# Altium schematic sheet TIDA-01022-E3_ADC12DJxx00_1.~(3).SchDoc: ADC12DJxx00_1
size 431 x 279 mm; Date: Not shown in title block; ApprovedBy: Not shown in title block; CheckedBy: Not shown in title block; Author: Not shown in title block; CompanyName: Not shown in title block; DrawnBy: Avinash N; Engineer: Not shown in title block; Organization: Not shown in title block; Address1: Not shown in title block; Address2: Not shown in title block; Address3: Not shown in title block; Address4: Not shown in title block; DocumentNumber: 1; Revision: Use project parameter SCH_Rev; SheetNumber: 6; SheetTotal: 26; PageSetup: Record=PageOptions¦CenterHorizontal=True¦CenterVertical=True¦PrintScale=1.00¦XCorrection=1.00¦YCorrection=1.00¦PrintKind=0¦BorderSize=5000000¦LeftOffset=0¦BottomOffset=0¦Orientation=2¦PaperLength=1000¦PaperWidth=1000¦Scale=100¦PaperSource=15¦PrintQuality=600¦MediaType=1¦DitherType=10¦PaperKind=Letter¦PrintScaleMode=1
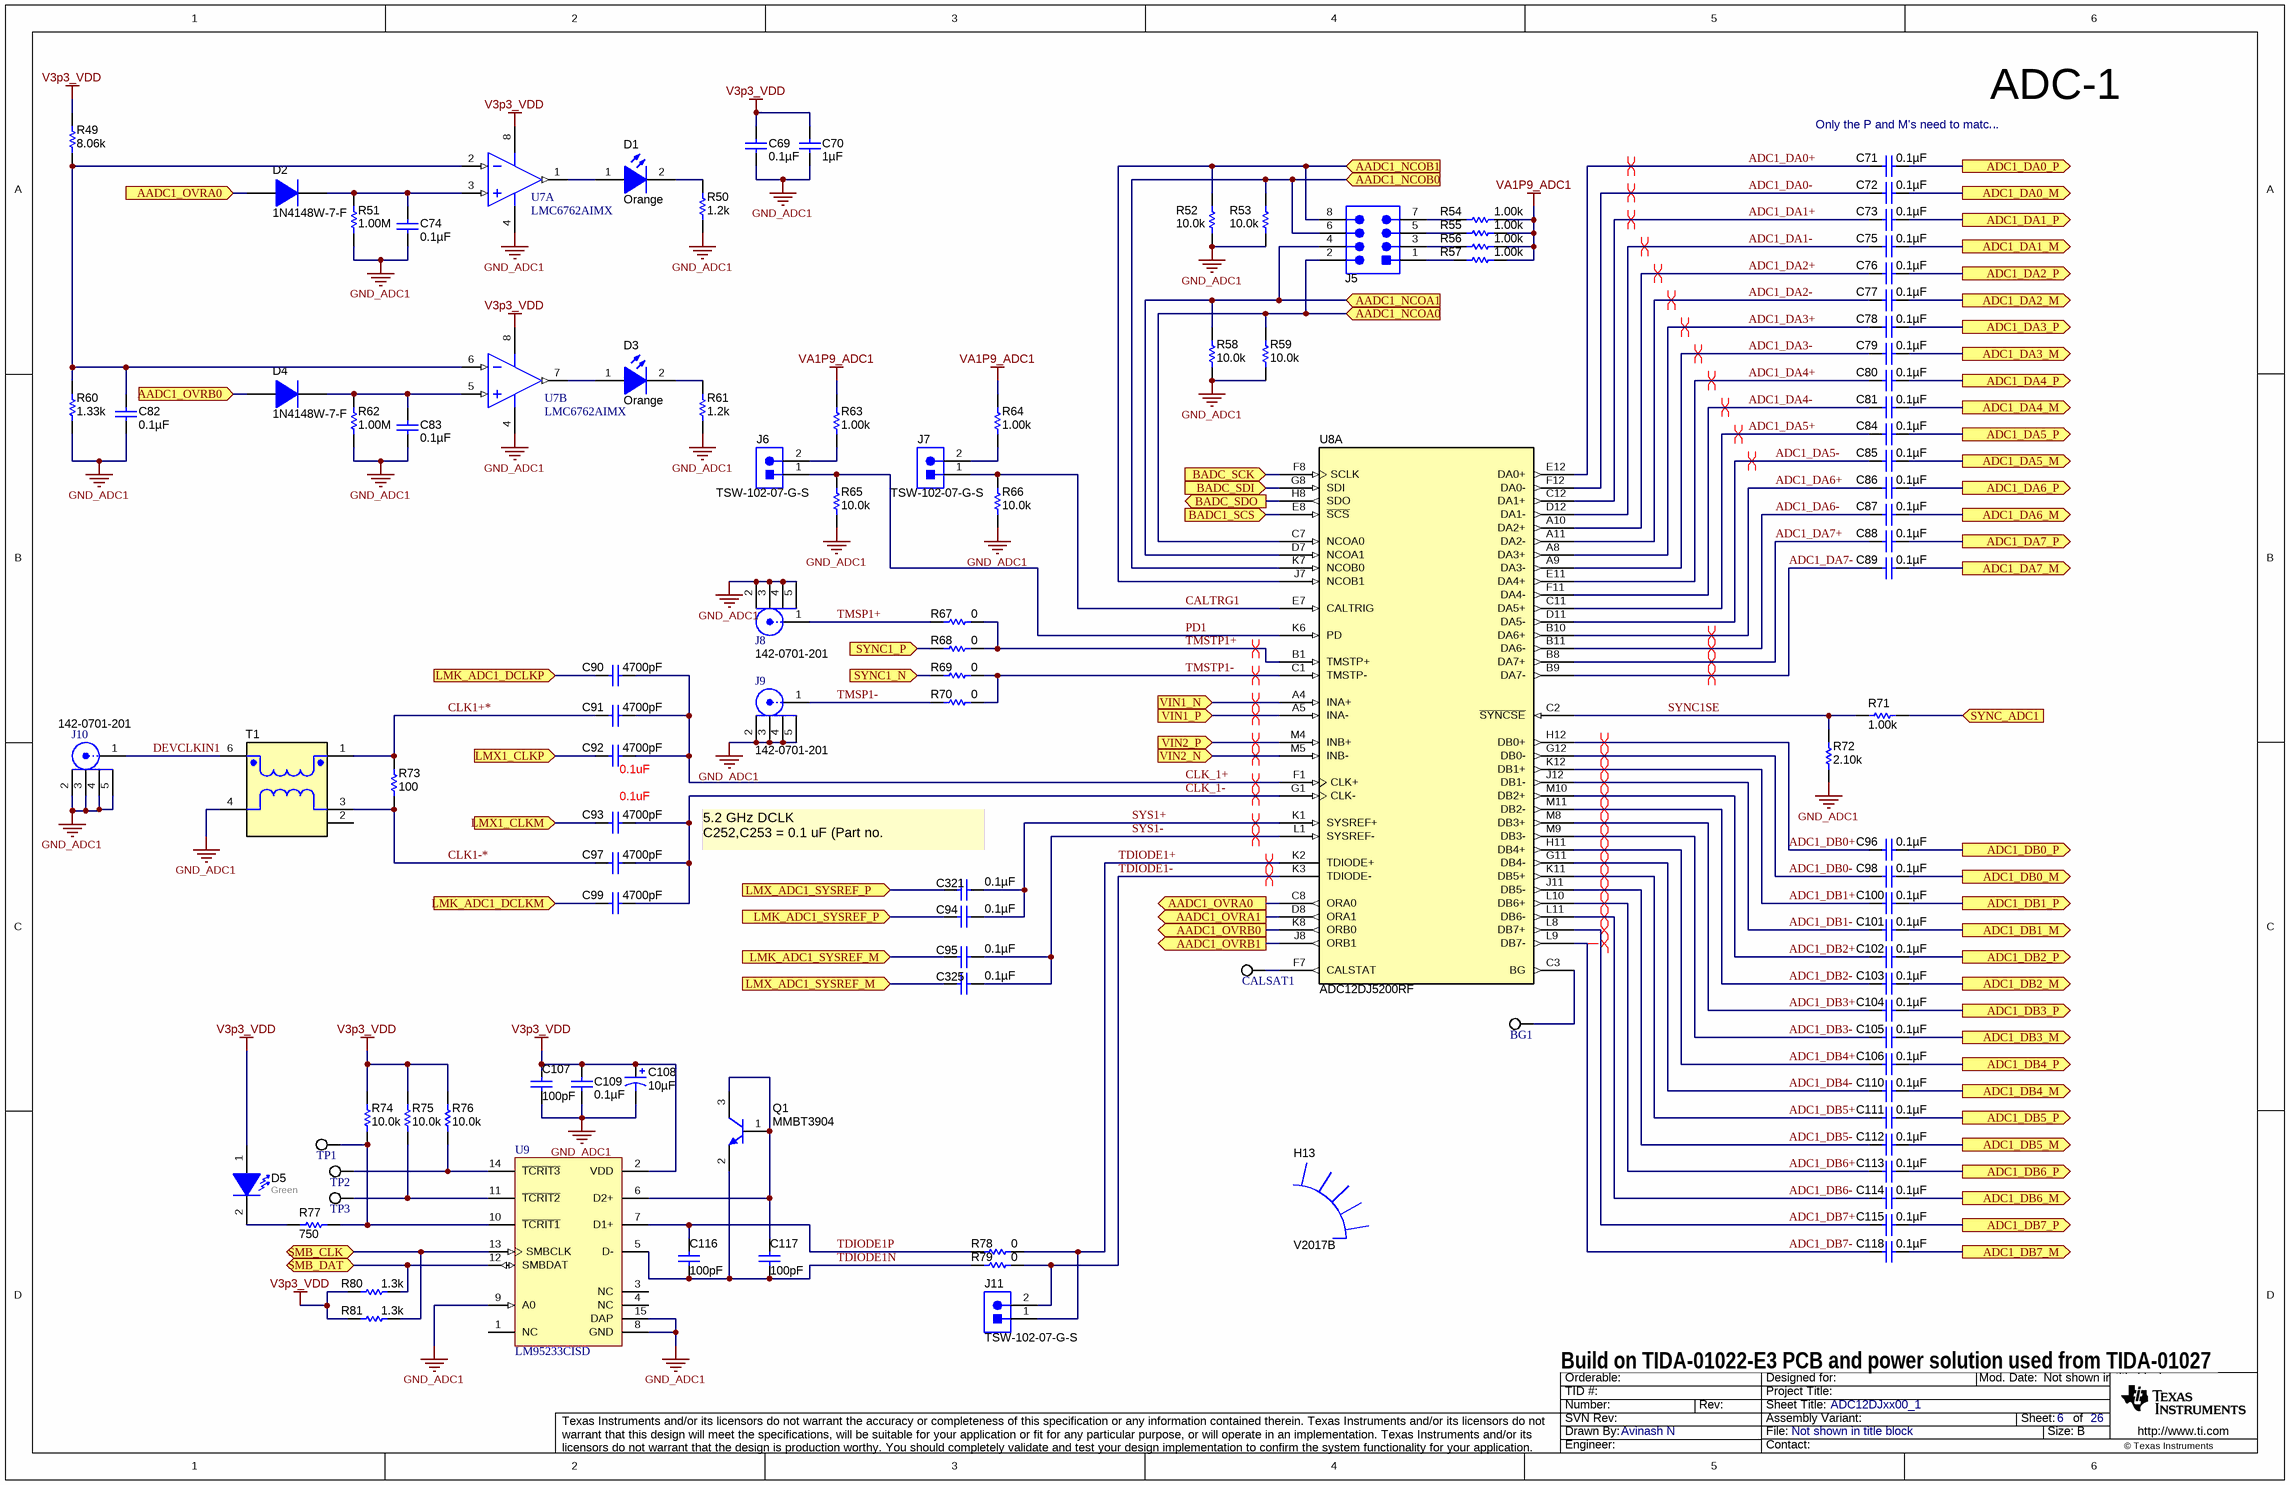
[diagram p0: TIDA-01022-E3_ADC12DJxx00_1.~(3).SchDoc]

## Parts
BG1  5002  [Keystone5002]  (value not drawn)
C69  ValueDisplayed: 0.1µF  [0402]  (hidden comment: C1005X7R1E104M050BB)
C70  ValueDisplayed: 1µF  [0603]  (hidden comment: C1608X5R1A105K080AC)
C71  ValueDisplayed: 0.1µF  [0201_adc]  (hidden comment: GRM033C71A104KE14D)
C72  ValueDisplayed: 0.1µF  [0201_adc]  (hidden comment: GRM033C71A104KE14D)
C73  ValueDisplayed: 0.1µF  [0201_adc]  (hidden comment: GRM033C71A104KE14D)
C74  ValueDisplayed: 0.1µF  [0402]  (hidden comment: C1005X7R1E104M050BB)
C75  ValueDisplayed: 0.1µF  [0201_adc]  (hidden comment: GRM033C71A104KE14D)
C76  ValueDisplayed: 0.1µF  [0201_adc]  (hidden comment: GRM033C71A104KE14D)
C77  ValueDisplayed: 0.1µF  [0201_adc]  (hidden comment: GRM033C71A104KE14D)
C78  ValueDisplayed: 0.1µF  [0201_adc]  (hidden comment: GRM033C71A104KE14D)
C79  ValueDisplayed: 0.1µF  [0201_adc]  (hidden comment: GRM033C71A104KE14D)
C80  ValueDisplayed: 0.1µF  [0201_adc]  (hidden comment: GRM033C71A104KE14D)
C81  ValueDisplayed: 0.1µF  [0201_adc]  (hidden comment: GRM033C71A104KE14D)
C82  ValueDisplayed: 0.1µF  [0402]  (hidden comment: C1005X7R1E104M050BB)
C83  ValueDisplayed: 0.1µF  [0402]  (hidden comment: C1005X7R1E104M050BB)
C84  ValueDisplayed: 0.1µF  [0201_adc]  (hidden comment: GRM033C71A104KE14D)
C85  ValueDisplayed: 0.1µF  [0201_adc]  (hidden comment: GRM033C71A104KE14D)
C86  ValueDisplayed: 0.1µF  [0201_adc]  (hidden comment: GRM033C71A104KE14D)
C87  ValueDisplayed: 0.1µF  [0201_adc]  (hidden comment: GRM033C71A104KE14D)
C88  ValueDisplayed: 0.1µF  [0201_adc]  (hidden comment: GRM033C71A104KE14D)
C89  ValueDisplayed: 0.1µF  [0201_adc]  (hidden comment: GRM033C71A104KE14D)
C90  ValueDisplayed: 4700pF  [0402]  (hidden comment: GRM155R71H472KA01D)
C91  ValueDisplayed: 4700pF  [0402]  (hidden comment: GRM155R71H472KA01D)
C92  ValueDisplayed: 4700pF  [0402]  (hidden comment: GRM155R71H472KA01D)
C93  ValueDisplayed: 4700pF  [0402]  (hidden comment: GRM155R71H472KA01D)
C94  ValueDisplayed: 0.1µF  [0402]  (hidden comment: C1005X7R1E104M050BB)
C95  ValueDisplayed: 0.1µF  [0402]  (hidden comment: C1005X7R1E104M050BB)
C96  ValueDisplayed: 0.1µF  [0201_adc]  (hidden comment: GRM033C71A104KE14D)
C97  ValueDisplayed: 4700pF  [0402]  (hidden comment: GRM155R71H472KA01D)
C98  ValueDisplayed: 0.1µF  [0201_adc]  (hidden comment: GRM033C71A104KE14D)
C99  ValueDisplayed: 4700pF  [0402]  (hidden comment: GRM155R71H472KA01D)
C100  ValueDisplayed: 0.1µF  [0201_adc]  (hidden comment: GRM033C71A104KE14D)
C101  ValueDisplayed: 0.1µF  [0201_adc]  (hidden comment: GRM033C71A104KE14D)
C102  ValueDisplayed: 0.1µF  [0201_adc]  (hidden comment: GRM033C71A104KE14D)
C103  ValueDisplayed: 0.1µF  [0201_adc]  (hidden comment: GRM033C71A104KE14D)
C104  ValueDisplayed: 0.1µF  [0201_adc]  (hidden comment: GRM033C71A104KE14D)
C105  ValueDisplayed: 0.1µF  [0201_adc]  (hidden comment: GRM033C71A104KE14D)
C106  ValueDisplayed: 0.1µF  [0201_adc]  (hidden comment: GRM033C71A104KE14D)
C107  ValueDisplayed: 100pF  [0402]  (hidden comment: GRM1555C1H101JA01D)
C108  ValueDisplayed: 10µF  [3528-21]  (hidden comment: 293D106X0010B2TE3)
C109  ValueDisplayed: 0.1µF  [0402]  (hidden comment: C1005X7R1E104M050BB)
C110  ValueDisplayed: 0.1µF  [0201_adc]  (hidden comment: GRM033C71A104KE14D)
C111  ValueDisplayed: 0.1µF  [0201_adc]  (hidden comment: GRM033C71A104KE14D)
C112  ValueDisplayed: 0.1µF  [0201_adc]  (hidden comment: GRM033C71A104KE14D)
C113  ValueDisplayed: 0.1µF  [0201_adc]  (hidden comment: GRM033C71A104KE14D)
C114  ValueDisplayed: 0.1µF  [0201_adc]  (hidden comment: GRM033C71A104KE14D)
C115  ValueDisplayed: 0.1µF  [0201_adc]  (hidden comment: GRM033C71A104KE14D)
C116  ValueDisplayed: 100pF  [0402]  (hidden comment: GRM1555C1H101JA01D)
C117  ValueDisplayed: 100pF  [0402]  (hidden comment: GRM1555C1H101JA01D)
C118  ValueDisplayed: 0.1µF  [0201_adc]  (hidden comment: GRM033C71A104KE14D)
C321  ValueDisplayed: 0.1µF  [0402]  (hidden comment: C1005X7R1E104M050BB)
C325  ValueDisplayed: 0.1µF  [0402]  (hidden comment: C1005X7R1E104M050BB)
CALSAT1  5002  [Keystone5002]  (value not drawn)
D1  value Orange  [LED_LTST-C190]  (hidden comment: LTST-C190KFKT)
D2  1N4148W-7-F  [SOD-123]
D3  value Orange  [LED_LTST-C190]  (hidden comment: LTST-C190KFKT)
D4  1N4148W-7-F  [SOD-123]
D5  value Green  [LED_LTST-C190]  (hidden comment: LTST-C190GKT)
H13  V2017B  [ASMN_V2017B]  (mechanical)
J5  TSW-104-07-G-D  [TSW-104-07-G-D]  (value not drawn)
J6  TSW-102-07-G-S  [TSW-102-07-G-S]
J7  TSW-102-07-G-S  [TSW-102-07-G-S]
J8  142-0701-201  [Johnson_142-0701-20x]
J9  142-0701-201  [Johnson_142-0701-20x]
J10  142-0701-201  [Johnson_142-0701-20x]
J11  TSW-102-07-G-S  [TSW-102-07-G-S]
Q1  MMBT3904  [SOT-23]
R49  ValueDisplayed: 8.06k  [0402]  (hidden comment: CRCW04028K06FKED)
R50  ValueDisplayed: 1.2k  [0402]  (hidden comment: CRCW04021K20JNED)
R51  ValueDisplayed: 1.00M  [0402]  (hidden comment: ERJ-2RKF1004X)
R52  ValueDisplayed: 10.0k  [0402]  (hidden comment: ERJ-2RKF1002X)
R53  ValueDisplayed: 10.0k  [0402]  (hidden comment: ERJ-2RKF1002X)
R54  ValueDisplayed: 1.00k  [0402]  (hidden comment: ERJ-2RKF1001X)
R55  ValueDisplayed: 1.00k  [0402]  (hidden comment: ERJ-2RKF1001X)
R56  ValueDisplayed: 1.00k  [0402]  (hidden comment: ERJ-2RKF1001X)
R57  ValueDisplayed: 1.00k  [0402]  (hidden comment: ERJ-2RKF1001X)
R58  ValueDisplayed: 10.0k  [0402]  (hidden comment: ERJ-2RKF1002X)
R59  ValueDisplayed: 10.0k  [0402]  (hidden comment: ERJ-2RKF1002X)
R60  ValueDisplayed: 1.33k  [0402]  (hidden comment: CRCW04021K33FKED)
R61  ValueDisplayed: 1.2k  [0402]  (hidden comment: CRCW04021K20JNED)
R62  ValueDisplayed: 1.00M  [0402]  (hidden comment: ERJ-2RKF1004X)
R63  ValueDisplayed: 1.00k  [0402]  (hidden comment: ERJ-2RKF1001X)
R64  ValueDisplayed: 1.00k  [0402]  (hidden comment: ERJ-2RKF1001X)
R65  ValueDisplayed: 10.0k  [0402]  (hidden comment: ERJ-2RKF1002X)
R66  ValueDisplayed: 10.0k  [0402]  (hidden comment: ERJ-2RKF1002X)
R67  ValueDisplayed: 0  [0402]  (hidden comment: CRCW04020000Z0ED)
R68  ValueDisplayed: 0  [0402]  (hidden comment: CRCW04020000Z0ED)
R69  ValueDisplayed: 0  [0402]  (hidden comment: CRCW04020000Z0ED)
R70  ValueDisplayed: 0  [0402]  (hidden comment: CRCW04020000Z0ED)
R71  ValueDisplayed: 1.00k  [0402]  (hidden comment: ERJ-2RKF1001X)
R72  ValueDisplayed: 2.10k  [0402]  (hidden comment: CRCW04022K10FKED)
R73  ValueDisplayed: 100  [0402]  (hidden comment: CRCW0402100RFKED)
R74  ValueDisplayed: 10.0k  [0402]  (hidden comment: ERJ-2RKF1002X)
R75  ValueDisplayed: 10.0k  [0402]  (hidden comment: ERJ-2RKF1002X)
R76  ValueDisplayed: 10.0k  [0402]  (hidden comment: ERJ-2RKF1002X)
R77  ValueDisplayed: 750  [0603]  (hidden comment: CRCW0603750RJNEA)
R78  ValueDisplayed: 0  [0402]  (hidden comment: CRCW04020000Z0ED)
R79  ValueDisplayed: 0  [0402]  (hidden comment: CRCW04020000Z0ED)
R80  ValueDisplayed: 1.3k  [0603]  (hidden comment: RC0603JR-071K3L)
R81  ValueDisplayed: 1.3k  [0603]  (hidden comment: RC0603JR-071K3L)
T1  TC1-1-43X+  [MNC_AT1521]  (value not drawn)
TP1  5002  [Keystone5002]  (value not drawn)
TP2  5002  [Keystone5002]  (value not drawn)
TP3  5002  [Keystone5002]  (value not drawn)
U7  LMC6762AIMX  [M08A_N]  (parts A,B of 2)
U8  ADC12DJ5200RF  [AAV0144A]  (part A of 2)
U9  LM95233CISD  [SDA14B]

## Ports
AADC1_NCOA0 (in), AADC1_NCOA1 (in), AADC1_NCOB0 (in), AADC1_NCOB1 (in), AADC1_OVRA0 (in), AADC1_OVRA0 (out), AADC1_OVRA1 (out), AADC1_OVRB0 (in), AADC1_OVRB0 (out), AADC1_OVRB1 (out), ADC1_DA0_M (out), ADC1_DA0_P (out), ADC1_DA1_M (out), ADC1_DA1_P (out), ADC1_DA2_M (out), ADC1_DA2_P (out), ADC1_DA3_M (out), ADC1_DA3_P (out), ADC1_DA4_M (out), ADC1_DA4_P (out), ADC1_DA5_M (out), ADC1_DA5_P (out), ADC1_DA6_M (out), ADC1_DA6_P (out), ADC1_DA7_M (out), ADC1_DA7_P (out), ADC1_DB0_M (out), ADC1_DB0_P (out), ADC1_DB1_M (out), ADC1_DB1_P (out), ADC1_DB2_M (out), ADC1_DB2_P (out), ADC1_DB3_M (out), ADC1_DB3_P (out), ADC1_DB4_M (out), ADC1_DB4_P (out), ADC1_DB5_M (out), ADC1_DB5_P (out), ADC1_DB6_M (out), ADC1_DB6_P (out), ADC1_DB7_M (out), ADC1_DB7_P (out), BADC1_SCS (in), BADC_SCK (in), BADC_SDI (in), BADC_SDO (out), LMK_ADC1_DCLKM (in), LMK_ADC1_DCLKP (in), LMK_ADC1_SYSREF_M (in), LMK_ADC1_SYSREF_P (in), LMX1_CLKM (in), LMX1_CLKP (in), LMX_ADC1_SYSREF_M (in), LMX_ADC1_SYSREF_P (in), SMB_CLK (bidir), SMB_DAT (bidir), SYNC1_N (in), SYNC1_P (in), SYNC_ADC1 (in), VIN1_N (in), VIN1_P (in), VIN2_N (in), VIN2_P (in)

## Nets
GND_ADC1: C69.1 C70.2 C74.1 C82.1 C83.1 C107.2 C108.2(-) C109.2 J8.2 J8.3 J8.4 J8.5 J9.2 J9.3 J9.4 J9.5 J10.2 J10.3 J10.4 J10.5 R50.1 R51.1 R52.2 R53.2 R58.2 R59.2 R60.1 R61.1 R62.1 R65.1 R66.1 R72.1 T1.4 U7.4(V-) U9.8(GND) U9.9(A0) U9.15(DAP)
V3p3_VDD: C69.2 C70.1 C107.1 C108.1(+) C109.1 D5.1(A) R49.2 R74.2 R75.2 R76.2 R80.2 R81.2 U7.8(V+) U9.2(VDD)
VA1P9_ADC1: R54.1 R55.1 R56.1 R57.1 R63.2 R64.2
AADC1_NCOA0: J5.2 R59.1 U8.C7(NCOA0) ; port AADC1_NCOA0
AADC1_NCOA1: J5.4 R58.1 U8.D7(NCOA1) ; port AADC1_NCOA1
AADC1_NCOB0: J5.6 R53.1 U8.K7(NCOB0) ; port AADC1_NCOB0
AADC1_NCOB1: J5.8 R52.1 U8.J7(NCOB1) ; port AADC1_NCOB1
AADC1_OVRA0: D2.2(A) U8.C8(ORA0) ; port AADC1_OVRA0
AADC1_OVRA1: U8.D8(ORA1) ; port AADC1_OVRA1
AADC1_OVRB0: D4.2(A) U8.K8(ORB0) ; port AADC1_OVRB0
AADC1_OVRB1: U8.J8(ORB1) ; port AADC1_OVRB1
ADC1_DA0+: C71.1 U8.E12(DA0+)
ADC1_DA0-: C72.1 U8.F12(DA0-)
ADC1_DA0_M: C72.2 ; port ADC1_DA0_M
ADC1_DA0_P: C71.2 ; port ADC1_DA0_P
ADC1_DA1+: C73.1 U8.C12(DA1+)
ADC1_DA1-: C75.1 U8.D12(DA1-)
ADC1_DA1_M: C75.2 ; port ADC1_DA1_M
ADC1_DA1_P: C73.2 ; port ADC1_DA1_P
ADC1_DA2+: C76.1 U8.A10(DA2+)
ADC1_DA2-: C77.1 U8.A11(DA2-)
ADC1_DA2_M: C77.2 ; port ADC1_DA2_M
ADC1_DA2_P: C76.2 ; port ADC1_DA2_P
ADC1_DA3+: C78.1 U8.A8(DA3+)
ADC1_DA3-: C79.1 U8.A9(DA3-)
ADC1_DA3_M: C79.2 ; port ADC1_DA3_M
ADC1_DA3_P: C78.2 ; port ADC1_DA3_P
ADC1_DA4+: C80.1 U8.E11(DA4+)
ADC1_DA4-: C81.1 U8.F11(DA4-)
ADC1_DA4_M: C81.2 ; port ADC1_DA4_M
ADC1_DA4_P: C80.2 ; port ADC1_DA4_P
ADC1_DA5+: C84.1 U8.C11(DA5+)
ADC1_DA5-: C85.1 U8.D11(DA5-)
ADC1_DA5_M: C85.2 ; port ADC1_DA5_M
ADC1_DA5_P: C84.2 ; port ADC1_DA5_P
ADC1_DA6+: C86.1 U8.B10(DA6+)
ADC1_DA6-: C87.1 U8.B11(DA6-)
ADC1_DA6_M: C87.2 ; port ADC1_DA6_M
ADC1_DA6_P: C86.2 ; port ADC1_DA6_P
ADC1_DA7+: C88.1 U8.B8(DA7+)
ADC1_DA7-: C89.1 U8.B9(DA7-)
ADC1_DA7_M: C89.2 ; port ADC1_DA7_M
ADC1_DA7_P: C88.2 ; port ADC1_DA7_P
ADC1_DB0+: C96.1 U8.H12(DB0+)
ADC1_DB0-: C98.1 U8.G12(DB0-)
ADC1_DB0_M: C98.2 ; port ADC1_DB0_M
ADC1_DB0_P: C96.2 ; port ADC1_DB0_P
ADC1_DB1+: C100.1 U8.K12(DB1+)
ADC1_DB1-: C101.1 U8.J12(DB1-)
ADC1_DB1_M: C101.2 ; port ADC1_DB1_M
ADC1_DB1_P: C100.2 ; port ADC1_DB1_P
ADC1_DB2+: C102.1 U8.M10(DB2+)
ADC1_DB2-: C103.1 U8.M11(DB2-)
ADC1_DB2_M: C103.2 ; port ADC1_DB2_M
ADC1_DB2_P: C102.2 ; port ADC1_DB2_P
ADC1_DB3+: C104.1 U8.M8(DB3+)
ADC1_DB3-: C105.1 U8.M9(DB3-)
ADC1_DB3_M: C105.2 ; port ADC1_DB3_M
ADC1_DB3_P: C104.2 ; port ADC1_DB3_P
ADC1_DB4+: C106.1 U8.H11(DB4+)
ADC1_DB4-: C110.1 U8.G11(DB4-)
ADC1_DB4_M: C110.2 ; port ADC1_DB4_M
ADC1_DB4_P: C106.2 ; port ADC1_DB4_P
ADC1_DB5+: C111.1 U8.K11(DB5+)
ADC1_DB5-: C112.1 U8.J11(DB5-)
ADC1_DB5_M: C112.2 ; port ADC1_DB5_M
ADC1_DB5_P: C111.2 ; port ADC1_DB5_P
ADC1_DB6+: C113.1 U8.L10(DB6+)
ADC1_DB6-: C114.1 U8.L11(DB6-)
ADC1_DB6_M: C114.2 ; port ADC1_DB6_M
ADC1_DB6_P: C113.2 ; port ADC1_DB6_P
ADC1_DB7+: C115.1 U8.L8(DB7+)
ADC1_DB7-: C118.1 U8.L9(DB7-)
ADC1_DB7_M: C118.2 ; port ADC1_DB7_M
ADC1_DB7_P: C115.2 ; port ADC1_DB7_P
BADC1_SCS: U8.E8(~{SCS}) ; port BADC1_SCS
BADC_SCK: U8.F8(SCLK) ; port BADC_SCK
BADC_SDI: U8.G8(SDI) ; port BADC_SDI
BADC_SDO: U8.H8(SDO) ; port BADC_SDO
CALTRG1: J7.1 R66.2 U8.E7(CALTRIG)
CLK1+*: C91.2 R73.2 T1.1
CLK1-*: C97.2 R73.1 T1.3
CLK_1+: C90.1 C91.1 C92.1 U8.F1(CLK+)
CLK_1-: C93.1 C97.1 C99.1 U8.G1(CLK-)
DEVCLKIN1: J10.1 T1.6
LMK_ADC1_DCLKM: C99.2 ; port LMK_ADC1_DCLKM
LMK_ADC1_DCLKP: C90.2 ; port LMK_ADC1_DCLKP
LMK_ADC1_SYSREF_M: C95.1 ; port LMK_ADC1_SYSREF_M
LMK_ADC1_SYSREF_P: C94.1 ; port LMK_ADC1_SYSREF_P
LMX1_CLKM: C93.2 ; port LMX1_CLKM
LMX1_CLKP: C92.2 ; port LMX1_CLKP
LMX_ADC1_SYSREF_M: C325.1 ; port LMX_ADC1_SYSREF_M
LMX_ADC1_SYSREF_P: C321.1 ; port LMX_ADC1_SYSREF_P
PD1: J6.1 R65.2 U8.K6(PD)
SMB_CLK: R81.1 U9.13(SMBCLK) ; port SMB_CLK
SMB_DAT: R80.1 U9.12(SMBDAT) ; port SMB_DAT
SYNC1_N: R69.1 ; port SYNC1_N
SYNC1_P: R68.1 ; port SYNC1_P
SYNC1SE: R71.1 R72.2 U8.C2(~{SYNCSE})
SYNC_ADC1: R71.2 ; port SYNC_ADC1
SYS1+: C94.2 C321.2 U8.K1(SYSREF+)
SYS1-: C95.2 C325.2 U8.L1(SYSREF-)
TDIODE1+: J11.1 R78.2 U8.K2(TDIODE+)
TDIODE1-: J11.2 R79.2 U8.K3(TDIODE-)
TDIODE1N: C116.2 C117.2 Q1.2(E) R79.1 U9.5(D-)
TDIODE1P: C116.1 R78.1 U9.7(D1+)
TMSP1+: J8.1 R67.1
TMSP1-: J9.1 R70.1
TMSTP1+: R67.2 R68.2 U8.B1(TMSTP+)
TMSTP1-: R69.2 R70.2 U8.C1(TMSTP-)
VIN1_N: U8.A4(INA+) ; port VIN1_N
VIN1_P: U8.A5(INA-) ; port VIN1_P
VIN2_N: U8.M5(INB-) ; port VIN2_N
VIN2_P: U8.M4(INB+) ; port VIN2_P
NetBG1_1: BG1.1 U8.C3(BG)
NetC74_2: C74.2 D2.1(K) R51.2 U7.3(INA+)
NetC82_2: C82.2 R49.1 R60.2 U7.2(INA-) U7.6(INB-)
NetC83_2: C83.2 D4.1(K) R62.2 U7.5(INB+)
NetC117_1: C117.1 Q1.1(B) Q1.3(C) U9.6(D2+)
NetCALSAT1_1: CALSAT1.1 U8.F7(CALSTAT)
NetD1_1: D1.1(A) U7.1(OUTA)
NetD1_2: D1.2(K) R50.2
NetD3_1: D3.1(A) U7.7(OUTB)
NetD3_2: D3.2(K) R61.2
NetD5_2: D5.2(K) R77.2
NetJ5_1: J5.1 R57.2
NetJ5_3: J5.3 R56.2
NetJ5_5: J5.5 R55.2
NetJ5_7: J5.7 R54.2
NetJ6_2: J6.2 R63.1
NetJ7_2: J7.2 R64.1
NetR74_1: R74.1 R77.1 TP1.1 U9.10(~{TCRIT1})
NetR75_1: R75.1 TP3.1 U9.11(~{TCRIT2})
NetR76_1: R76.1 TP2.1 U9.14(~{TCRIT3})

Not connected (* = marked no-connect by the designer): T1 2; U9 1(NC) 3(NC) 4(NC)

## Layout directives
differential pair: ADC1_DA0+, ADC1_DA0-, ADC1_DA1+, ADC1_DA1-, ADC1_DA2+, ADC1_DA2-, ADC1_DA3+, ADC1_DA3-, ADC1_DA4+, ADC1_DA4-, ADC1_DA5+, ADC1_DA5-, ADC1_DA6+, ADC1_DA6-, ADC1_DA7+, ADC1_DA7-, ADC1_DB0+, ADC1_DB0-, ADC1_DB1+, ADC1_DB1-, ADC1_DB2+, ADC1_DB2-, ADC1_DB3+, ADC1_DB3-, ADC1_DB4+, ADC1_DB4-, ADC1_DB5+, ADC1_DB5-, ADC1_DB6+, ADC1_DB6-, ADC1_DB7+, ADC1_DB7-, CLK_1+, CLK_1-, SYS1+, SYS1-, TDIODE1+, TDIODE1-, TMSTP1+, TMSTP1-, VIN1_N, VIN1_P, VIN2_N, VIN2_P

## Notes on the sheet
- (near C71) Only the P and M's need to match.
- ADC-1
- (near C92) 0.1uF
- 0.1uF
- (near C321) 5.2 GHz DCLK
  C252,C253 = 0.1 uF (Part no. 530Z104KT10T))
- Build on TIDA-01022-E3 PCB and power solution used from TIDA-01027

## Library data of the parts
BG1 CALSAT1 TP1-TP3 = 5002: Test Point, Miniature, White, TH; Manufacturer: Keystone; CompType: Test Point Loop; ContactFinish: Silver; Green_Lifecycle: Active; Green_REACh: Passed
C69 C74 C82 C83 C94 C95 C109 C321 C325 = C1005X7R1E104M050BB: CAP, CERM, 0.1 µF, 25 V, +/- 20%, X7R, 0402; Manufacturer: TDK; Polarized: N; TaMax_C: 125; TaMin_C: -55; Tolerance_%: 20; VDC_V: 25; Cap_F: 0.0000001; CompType: Capacitor; Value: 0.1uF; Value1: Unknown; Value2: 25V; U/M: EA; SizeArea_mm2: 0.5; SizeAreaWB_mm2: 3; SizeX_mm: 1; SizeZ_mm: 0.6; AEC Category: Q200
C70 = C1608X5R1A105K080AC: CAP, CERM, 1 µF, 10 V, +/- 10%, X5R, 0603; Manufacturer: TDK; Polarized: N; CompType: Capacitor; Value: 1uF; U/M: EA; Cap_F: 0.000001; Tolerance_%: 10; Value1: Unknown; Value2: 10V; TaMin_C: -55; TaMax_C: 85; SizeArea_mm2: 1.28; SizeAreaWB_mm2: 4.68; SizeX_mm: 1.6; SizeY_mm: 0.8; SizeZ_mm: 1; AEC Category: Q200
C71-C73 C75-C81 C84-C89 C96 C98 C100-C106 C110-C115 C118 = GRM033C71A104KE14D: CAP, CERM, 0.1 µF, 10 V, +/- 10%, X7S, 0201; Manufacturer: MuRata; Cap_Case: 0201; Polarized: N; TaMax_C: 125; TaMin_C: -55; Tolerance_%: 10; Cap_F: 0.0000001; CompType: Capacitor; Value: 0.1uF; Value1: Unknown; Value2: 10V; U/M: EA; SizeArea_mm2: 0.18; SizeAreaWB_mm2: 2.08; SizeX_mm: 0.6; SizeY_mm: 0.3; SizeZ_mm: 0.26; AEC Category: Q200
C90-C93 C97 C99 = GRM155R71H472KA01D: CAP, CERM, 4700 pF, 50 V, +/- 10%, X7R, 0402; Manufacturer: MuRata; Polarized: N; CompType: Capacitor; Value: 4700pF; U/M: EA; Cap_F: 0.0000000047; Tolerance_%: 10; Value1: Unknown; VDC_V: 50; Value2: 50V; TaMin_C: -55; TaMax_C: 125; SizeArea_mm2: 0.5; SizeAreaWB_mm2: 3; SizeX_mm: 1; SizeZ_mm: 0.6; AEC Category: Q200
C107 C116 C117 = GRM1555C1H101JA01D: CAP, CERM, 100 pF, 50 V, +/- 5%, C0G/NP0, 0402; Manufacturer: MuRata; Polarized: N; CompType: Capacitor; Value: 100pF; U/M: EA; Cap_F: 0.0000000001; Tolerance_%: 5; Value1: Unknown; VDC_V: 50; Value2: 50V; TaMin_C: -55; TaMax_C: 125; SizeArea_mm2: 0.5; SizeAreaWB_mm2: 3; SizeX_mm: 1; SizeZ_mm: 0.6; AEC Category: Q200
C108 = 293D106X0010B2TE3: CAP, TA, 10 µF, 10 V, +/- 20%, 2.5 ohm, SMD; Manufacturer: Vishay-Sprague; Polarized: Y; CompType: Capacitor; Value: 10uF; U/M: EA; Cap_F: 0.00001; Tolerance_%: 20; Value1: 2.5 ohm; VDC_V: 10; Value2: 10V; ESR_ohm: 2.5; IRMS_A: 0.18; TaMin_C: -55; TaMax_C: 125; Cap_Case: B; SizeAreaWB_mm2: 17.1; SizeArea_mm2: 9.8; SizeX_mm: 3.5; SizeY_mm: 2.8; SizeZ_mm: 2.1; AEC Category: Q200
D1 D3 = LTST-C190KFKT: LED, Orange, SMD; Manufacturer: Lite-On; Type: AlInGaP; Vf_V: 2; Value2: 2V; Io_A: 0.02; Power_TotalModule: 0.075; Value1: 0.075W; U/M: EA
D2 D4 = 1N4148W-7-F: Diode, Ultrafast, 100 V, 0.15 A, SOD-123; Manufacturer: Diodes Inc.; U/M: EA; Vf_V: 1.25; Value: 100V; Value1: 0.15A; Value2: 1.25V; Io_A: 0.15; Vr_V: 100; TJmax_C: 150; SizeAreaWB_mm2: 13.095; SizeArea_mm2: 6.545; SizeX_mm: 3.85; SizeY_mm: 1.7; SizeZ_mm: 1.35; AEC Category: Q101
D5 = LTST-C190GKT: LED, Green, SMD; Manufacturer: Lite-On; Vf_V: 2.1; Value2: 2.1V; Io_A: 0.02; Power_TotalModule: 0.1; Value1: 0.1W; U/M: EA
H13 = V2017B: Heatsink, 10X10X7 mm; Manufacturer: Assman WSW; SymbolCreator: a0412235
J5 = TSW-104-07-G-D: Header, 100mil, 4x2, Gold, TH; Manufacturer: Samtec; SymbolCreator: a0411947; Pitch_mm: 2.54; Gender: Male; Shrouded: N; Row_Count: 2; Current_A: 6.3; Voltage_V: 550; Cert_CSA: Y
J6 J7 J11 = TSW-102-07-G-S: Header, 100mil, 2x1, Gold, TH; Manufacturer: Samtec; SymbolCreator: a0412235; Pitch_mm: 2.54; Gender: Male; Shrouded: N; Row_Count: 1; Current_A: 6.3; Voltage_V: 550; Cert_CSA: Y
J8 J9 = 142-0701-201: Connector, TH, SMA; Manufacturer: Emerson Network Power; SymbolCreator: X0208326
J10 = 142-0701-201: Connector, SMA, TH; Manufacturer: Cinch Connectivity; SymbolCreator: X0208326; Green_Lifecycle: Not Set; Green_REACh: Incomplete
Q1 = MMBT3904, Fairchild Semiconductor: Transistor, NPN, 40 V, 0.2 A, SOT-23; CompType: BJT; PNP: 0; NPN: 1; Vceo_V: 40; Vcesat1_V: 0.2; Value: 40 V; Value1: 0.2 A; HfeMax: 300; TaMin_C: -55; TaMax_C: 150; SizeAreaWB_mm2: 14; SizeArea_mm2: 7.5; SizeX_mm: 2.5; SizeY_mm: 3; SizeZ_mm: 1.1; U/M: EA; AEC Category: Q101
R49 = CRCW04028K06FKED: RES, 8.06 k, 1%, 0.063 W, 0402; Manufacturer: Vishay-Dale; CompType: Resistor; Value: 8.06k; Res_ohm: 8060; Value_Code: 8k06; Tolerance_%: 1; Power_W: 0.063; Value2: 0.063W; VDC_V: 50; TempCo: 100 ppm/C; SizeArea_mm2: 0.5; SizeZ_mm: 0.6; EIA_Code: E96; U/M: EA; AEC Category: Q200
R50 R61 = CRCW04021K20JNED: RES, 1.2 k, 5%, 0.063 W, 0402; Manufacturer: Vishay-Dale; CompType: Resistor; Value: 1.2k; Res_ohm: 1200; Value_Code: 1k20; Tolerance_%: 5; Power_W: 0.063; Value2: 0.063W; VDC_V: 50; TempCo: 200 ppm/C; SizeArea_mm2: 0.5; SizeX_mm: 1; SizeZ_mm: 0.6; EIA_Code: E24; U/M: EA; AEC Category: Q200
R51 R62 = ERJ-2RKF1004X: RES, 1.00 M, 1%, 0.1 W, 0402; Manufacturer: Panasonic; CompType: Resistor; Value: 1.00Meg; Res_ohm: 1000000; Value_Code: 1M00; Tolerance_%: 1; Power_W: 0.1; Value2: 0.1W; VDC_V: 50; TempCo: 100 ppm/C; SizeArea_mm2: 0.5; SizeZ_mm: 0.6; EIA_Code: E96; U/M: EA; AEC Category: Q200
R52 R53 R58 R59 R65 R66 R74-R76 = ERJ-2RKF1002X: RES, 10.0 k, 1%, 0.1 W, 0402; Manufacturer: Panasonic; CompType: Resistor; Value: 10.0k; Res_ohm: 10000; Value_Code: 10k0; Tolerance_%: 1; Power_W: 0.1; Value2: 0.1W; VDC_V: 50; TempCo: 100 ppm/C; SizeArea_mm2: 0.5; SizeZ_mm: 0.6; EIA_Code: E96; U/M: EA; AEC Category: Q200
R54-R57 R63 R64 R71 = ERJ-2RKF1001X: RES, 1.00 k, 1%, 0.1 W, 0402; Manufacturer: Panasonic; CompType: Resistor; Value: 1.00k; Res_ohm: 1000; Value_Code: 1k00; Tolerance_%: 1; Power_W: 0.1; Value2: 0.1W; VDC_V: 50; TempCo: 100 ppm/C; SizeArea_mm2: 0.5; SizeZ_mm: 0.6; EIA_Code: E96; U/M: EA; AEC Category: Q200
R60 = CRCW04021K33FKED: RES, 1.33 k, 1%, 0.063 W, 0402; Manufacturer: Vishay-Dale; CompType: Resistor; Value: 1.33k; Res_ohm: 1330; Value_Code: 1k33; Tolerance_%: 1; Power_W: 0.063; Value2: 0.063W; VDC_V: 50; TempCo: 100 ppm/C; SizeArea_mm2: 0.5; SizeZ_mm: 0.6; EIA_Code: E96; U/M: EA; AEC Category: Q200
R67-R70 R78 R79 = CRCW04020000Z0ED: RES, 0, 5%, 0.063 W, 0402; Manufacturer: Vishay-Dale; CompType: Resistor; Value: 0; Value_Code: 0000; Tolerance_%: 5; Power_W: 0.063; Value2: 0.063W; VDC_V: 50; TempCo: 200 ppm/C; SizeArea_mm2: 0.5; SizeX_mm: 1; SizeZ_mm: 0.6; EIA_Code: E24; U/M: EA; AEC Category: Q200
R72 = CRCW04022K10FKED: RES, 2.10 k, 1%, 0.063 W, 0402; Manufacturer: Vishay-Dale; CompType: Resistor; Value: 2.10k; Res_ohm: 2100; Value_Code: 2k10; Tolerance_%: 1; Power_W: 0.063; Value2: 0.063W; VDC_V: 50; TempCo: 100 ppm/C; SizeArea_mm2: 0.5; SizeZ_mm: 0.6; EIA_Code: E96; U/M: EA; AEC Category: Q200
R73 = CRCW0402100RFKED: RES, 100, 1%, 0.063 W, 0402; Manufacturer: Vishay-Dale; CompType: Resistor; Value: 100; Value_Code: 100R; Tolerance_%: 1; Power_W: 0.063; Value2: 0.063W; VDC_V: 50; TempCo: 100 ppm/C; SizeArea_mm2: 0.5; SizeZ_mm: 0.6; EIA_Code: E96; U/M: EA; AEC Category: Q200
R77 = CRCW0603750RJNEA: RES, 750, 5%, 0.1 W, 0603; Manufacturer: Vishay-Dale; CompType: Resistor; Value: 750; Value_Code: 750R; Tolerance_%: 5; Power_W: 0.1; Value2: 0.1W; VDC_V: 75; TempCo: 200 ppm/C; SizeArea_mm2: 1.28; SizeX_mm: 1.6; SizeY_mm: 0.8; SizeZ_mm: 1; EIA_Code: E24; U/M: EA; AEC Category: Q200
R80 R81 = RC0603JR-071K3L: RES, 1.3 k, 5%, 0.1 W, 0603; Manufacturer: Yageo America; CompType: Resistor; Value: 1.3k; Res_ohm: 1300; Value_Code: 1k30; Tolerance_%: 5; Power_W: 0.1; Value2: 0.1W; VDC_V: 50; TempCo: 100 ppm/C; SizeArea_mm2: 1.28; SizeX_mm: 1.6; SizeY_mm: 0.8; SizeZ_mm: 1; EIA_Code: E24; U/M: EA; AEC Category: Q200
T1 = TC1-1-43X+: RF Transformer, 50 ohm, SMT; Manufacturer: Minicircuits; SymbolCreator: Altium
U7 = LMC6762AIMX: Dual Micro-Power Rail-to-Rail Input CMOS Comparator with Push-Pull Output, 8-pin Narrow SOIC; PartNumber: LMC6762AIM/NOPB-ND; Manufacturer: Texas Instruments; PackageTopMarking: NSZXTT*LMC67*62AIM; PowerWise: N
U8 = ADC12DJ3200AAVR: 6.4-GSPS Single Channel or 3.2-GSPS Dual Channel 12-bit Analog-to-Digital Converter (ADC) Family, AAV0144A (FCBGA-144); Manufacturer: Texas Instruments; SymbolCreator: Altium; SizeArea_mm2: 100; SizeAreaWB_mm2: 144; SizeX_mm: 10; SizeZ_mm: 1.94; CompType: IC; U/M: EA
U9 = LM95233CISD: Dual Remote Diode and Local Temperature Sensor with SMBus Interface and TruTherm Technology, 15-pin LLP; PartNumber: LM95233CISD/NOPB; Manufacturer: Texas Instruments; PackageTopMarking: NS*UZXYTT*95233CI; PowerWise: Y; CompType: Temp Sensor IC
